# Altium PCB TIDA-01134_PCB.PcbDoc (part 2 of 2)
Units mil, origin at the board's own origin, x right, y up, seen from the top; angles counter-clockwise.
Board outline 4724.41 x 2283.46 mil, 2 copper layers (Top Layer, Bottom Layer), stack 62 mil thick; 90 components, 33 nets, 177 pads, 316 vias.
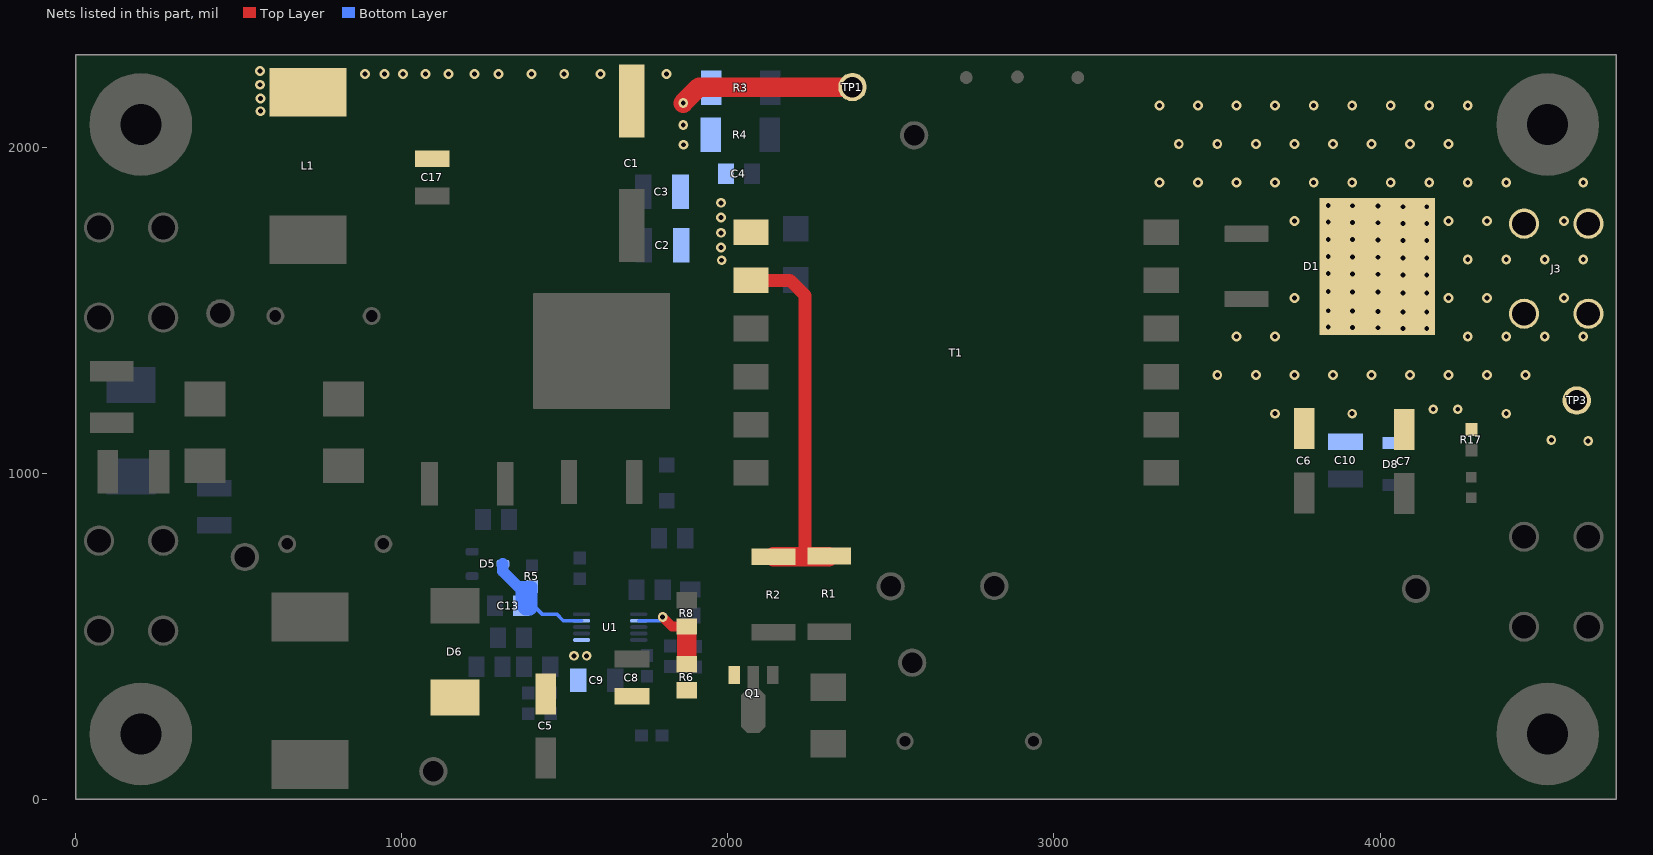
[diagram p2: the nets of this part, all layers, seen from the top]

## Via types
v1: diameter 30, hole 15, Top Layer to Bottom Layer, 316 vias

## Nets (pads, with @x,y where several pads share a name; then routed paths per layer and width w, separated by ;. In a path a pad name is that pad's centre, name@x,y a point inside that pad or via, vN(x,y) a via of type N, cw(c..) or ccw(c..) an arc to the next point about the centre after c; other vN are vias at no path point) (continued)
UVLO: R6.1 R8.2 U1.7 | length 233.5
  Top Layer w30: v1(1800,559) 1829,530 R8.2@1874,530
  Top Layer w60: R6.1@1874,427 R8.2@1874,508
  Bottom Layer w11: U1.7@1726.6,547.68 1792.68,547.68 v1@1793,548
VCC: C13.1 D5.3 R5.1 U1.4 | length 458.7
  Bottom Layer w11: 1410,588 1430,568 1475,568 1495.32,547.68 U1.4@1551.4,547.68
  Bottom Layer w35: D5.3@1310.24,722 1310.24,698.76 1356.5,652.5 ; 1356.5,652.5 R5.1@1399,652.5 1399,586 1394,581 1379,581 C13.1@1366,594 1366,643 1356.5,652.5
VIN: C5.1 C8.1 C9.1 D6.1 Q1.3 R6.2 U1.1
  other v1: 1528,440 1567,440
VIN_FILT: C1.1 C2.1 C3.1 C4.1 C17.1 L1.2 R1.2 R2.2 R3.2 R4.2 T1.1 T1.2 TP1.1 | length 1684.3
  Top Layer w40: T1.2@2071.06,1591.46 2190.54,1591.46 2237,1545 2237,757 ; R1.2@2309,744.14 R1.2@2311,746.14
  Top Layer w60: v1(1863,2135) 1912,2184 TP1.1@2382,2184 ; R2.2@2140,744.14 R1.2@2309,744.14
  other v1: 1981,1653 1979,1692 1979,1737 1979,1784 1979,1829 1864,2007 1863,2068 567,2110 567,2149 565,2191 887,2224 947,2224 1004,2224 1073,2224 1143,2224 1223,2224 1297,2224 1398,2224 1498,2224 1609,2224 1812,2224 565,2233
VOUT: C6.1 C7.1 C10.1 D1.4 D8.1 J3.1 J3.2 J3.3 J3.4 R17.2 TP3.1
  other v1: 4638,1099 4525,1102 3678.08,1182.53 3914.3,1182.53 4386.74,1182.53 4163,1196 4238,1196 3500.91,1300.64 3619.02,1300.64 3737.13,1300.64 3855.24,1300.64 3973.35,1300.64 4091.46,1300.64 4209.57,1300.64 4327.68,1300.64 4445.79,1300.64 3559.97,1418.76 3678.08,1418.76 4268.63,1418.76 4386.74,1418.76 4504.85,1418.76 4622.96,1418.76 4070,1444 4143,1444 3993,1446 3915,1447 3841,1448 4070,1494 4143,1494 3993,1496 3915,1497 3841,1498 3737.13,1536.87 4209.57,1536.87 4327.68,1536.87 4563.9,1536.87 4070,1553 4143,1553 3993,1555 3915,1556 3841,1557 4070,1608 4143,1608 3993,1610 3915,1611 3841,1612 4268.63,1654.98 4386.74,1654.98 4504.85,1654.98 4622.96,1654.98 4070,1660 4143,1660 3993,1662 3915,1663 3841,1664 4070,1713 4143,1713 3993,1715 3915,1716 3841,1717 4070,1766 4143,1766 3993,1768 3915,1769 3841,1770 3737.13,1773.09 4209.57,1773.09 4327.68,1773.09 4563.9,1773.09 4070,1817 4143,1817 3993,1819 3915,1820 3841,1821 3323.75,1891.2 3441.86,1891.2 3559.97,1891.2 3678.08,1891.2 3796.19,1891.2 3914.3,1891.2 4032.41,1891.2 4150.52,1891.2 4268.63,1891.2 4386.74,1891.2 4622.96,1891.2 3382.8,2009.31 3500.91,2009.31 3619.02,2009.31 3737.13,2009.31 3855.24,2009.31 3973.35,2009.31 4091.46,2009.31 4209.57,2009.31 3323.75,2127.42 3441.86,2127.42 3559.97,2127.42 3678.08,2127.42 3796.19,2127.42 3914.3,2127.42 4032.41,2127.42 4150.52,2127.42 4268.63,2127.42
pads on no net: D1.1 D5.2 FID1.1 FID2.1 FID3.1 H1.1 H2.1 H3.1 H4.1 H5.0 H6.0 H7.0 H8.0 LBL1.0 T1.9 T1.10

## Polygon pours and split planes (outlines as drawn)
CS_RS on Top Layer "TOP_LAYER_CS_RS_P082" (solid, remove dead copper, pour order 82): 1288,1036 1298,1046 1382,1046 1398,1030 1398,877 1398,835 1388,825 1353.54,825 1292,886.54 1292,982 1290,984
VIN_FILT on Top Layer "TOP_LAYER_VIN_FILT_P034" (solid, remove dead copper, pour order 34): 542,2112 571.5,2082.5 867,2082.5 912,2052 912,1983 966,1936 1146,1936 1192,1976 1817,1976 1949,1844 1949,1586 1987,1548 2210,1548 2256,1594 2256,1993 2322,2059 2323,2060 2323,2283.46 572.46,2283.46 542,2253
NetC16_1 on Top Layer "TOP_LAYER_NETC16_1_P028" (solid, remove dead copper, pour order 28): 638,1804 560,1804 527,1771 527,1476 574,1429 609,1429 669,1369 682,1369 737,1314 737,1184 760,1161 921,1161 945,1185 945,1307 879,1373 799,1373 764,1408 764,1514 764,1590 788,1614 800,1626 835,1626 865,1656 865,1778 839,1804 637,1804
NetC19_2 on Top Layer "TOP_LAYER_NETC19_2_P026" (solid, remove dead copper, pour order 26): 793,1075.79 750.79,1075.79 721,1046 721,1026 623,928 623,669 588,634 512,634 481,603 481,502 510,473 905,473 929,497 929,623 916,636 799,636 763,672 763,800 763,905 805,947 901,947 920,966 920,1055 900.16,1074.84
NetC18_1 on Top Layer "TOP_LAYER_NETC18_1_P024" (solid, remove dead copper, pour order 24): 367,1349 299,1281 299,1192 329,1162 539,1162 563,1186 563,1315 529,1349 367,1349
48V- on Top Layer "TOP_LAYER_48V-_P020" (solid, remove dead copper, pour order 20): 228,1080.77 285.23,1080.77 451.23,1080.77 487,1045 487,788 456,757 380,757 324,701 324,-2 4,-2 2,0 0,2 0,825 26,851 206,851 224,869 224,916 224,1075.77 229,1080.77
NetC22_2 on Top Layer "TOP_LAYER_NETC22_2_P002" (solid, remove dead copper, pour order 2): 47,1194 0,1147 0,981 46,935 132,935 132,1104 145.69,1114 173,1114 184,1125 184,1180 170,1194
48V+ on Top Layer "TOP_LAYER_48V+_P000" (solid, remove dead copper, pour order 0): -2,2284 0,2282 0,1318 0,1312 30,1282 31,1283 182,1283 255,1356 255,1396 348,1489 348,2283.46
NetQ2_1 on Top Layer "TOP_LAYER_NETQ2_1_P036" (solid, remove dead copper, pour order 36): 1484,1040 1499,1055 1503,1055 1578,1055 1601,1032 1601,906 1586,891 1492,891 1484,899
SW_NODE on Top Layer "TOP_LAYER_SW_NODE_P048" (solid, remove dead copper, pour order 48): 1232.87,1699 1161,1622.94 1161,1138 1194,1105 1756.31,1105 1870,1191.76 1870,1205 1913,1255 2137,1255 2171,1289 2171,1447 2135,1483 1983,1483 1946,1483 1853,1576 1637,1576 1514,1699
VIN on Top Layer "TOP_LAYER_VIN_P050" (solid, remove dead copper, pour order 50): 1491,470 1491.45,469.55 1585,469.55 1596,458.55 1596,349 1604,341 1808,341 1821,341 1839,359 1952,359 1990,397 2001,408 2036,408 2036,350 2034,348 1987,348 1917,278 1537,278 1510,251 1065,251 1027,289 1027,331 1066,370 1362,370 1381,389 1381,419 1431,469
NetD3_1 on Top Layer "TOP_LAYER_NETD3_1_P054" (solid, remove dead copper, pour order 54): 2244,540 2244,549 2257,562 2380,562 2414,528 2414,328 2388,302 2221,302 2170,353 2121,353 2119,355 2119,407 2129,417 2232,417 2244,429
GND on Top Layer "TOP_LAYER_GND_P064" (solid, remove dead copper, pour order 64): -3,2288 3,2282 2256,2282 2256,1 2255,0 2252,3 0,3
NetD1_3 on Top Layer "TOP_LAYER_NETD1_3_P068" (solid, remove dead copper, pour order 68): 3263.39,1546 3427.58,1546 3488.63,1484.95 3638.64,1484.95 3663,1509.31 3663,1751 3617,1797 3232.39,1797 3201.39,1766 3201.39,1578
VOUT on Top Layer "TOP_LAYER_VOUT_P070" (solid, remove dead copper, pour order 70): 3462.83,1295 3497.83,1260 3527,1260 3634,1164 3634,1109.65 3679.47,1071 4718.41,1071 4718.41,2280.59 4717,2282 3282,2282 3207,2207 3207,1876.45 3256.43,1845 3650.7,1845 3714,1789 3714,1490.35 3662,1438.35 3487,1438.35 3462.83,1414.17
ISO_GND on Top Layer "TOP_LAYER_ISO_GND_P074" (solid, remove dead copper, pour order 74): 3211,3 4713,2 4716,-1 4716,1005 3211,1005 3211,5 3209,3
GND on Top Layer "TOP_LAYER_GND_LV" (solid, remove dead copper, pour order 58): 1056,664 957,565 957,222 917,182 576,182 576,-2 2541,-2 2572,29 2572,274 2420,329 2187,329 2129,387 2129,533 2129,653 1045,653
ISO_GND on Top Layer "TOP_LAYER_ISO_GND_P080" (solid, remove dead copper, pour order 80): 3262,1187 3213,1138 3208,1138 3209,1137 3209,921 3268,862 3430,862 3506,862 3561,917 3561,1133 3505,1189 3264,1189
GND on Bottom Layer "BOTTOM_LAYER_GND_LV" (solid, remove dead copper, pour order 78): 1056,664 957,565 957,222 917,182 576,182 576,-2 2541,-2 2572,29 2572,274 2420,329 2187,329 2129,387 2129,533 2129,653 1045,653
EARTH on Bottom Layer "BOTTOM_LAYER_EARTH_P032" (solid, remove dead copper, pour order 32): 931,1571 898,1538 898,1390 898,1377 847,1326 773,1326 689,1242 689,1027 761,955 855,955 900,910 900,734 936,698 965,698 990,723 990,1537 956,1571 930,1571
48V- on Bottom Layer "BOTTOM_LAYER_48V-_P006" (solid, remove dead copper, pour order 6): -2,832 31,865 36,865 479,865 524,820 524,0 1,0
48V+ on Bottom Layer "BOTTOM_LAYER_48V+_P004" (solid, remove dead copper, pour order 4): 0,1265 0,1252 37,1215 244,1215 284,1255 284,1366 287,1369 332,1414 332,2283.46 3,2283.46
VIN_FILT on Bottom Layer "BOTTOM_LAYER_VIN_FILT_P038" (solid, remove dead copper, pour order 38): 1925,2283 1938,2283 1986,2235 1986,1983 2021,1948 2021,1649 2005,1633 1845,1633 1825,1653 1825,2244.46 1864,2283.46
SW_NODE on Bottom Layer "BOTTOM_LAYER_SW_NODE_P040" (solid, remove dead copper, pour order 40): 1306,1140 1838,1140 1918,1220 2230,1220 2359,1349 2360,1348 2360,1319 2360,1575 2302,1633 2140,1633 2082,1575 1640,1575 1593,1622 1593,1765 1544,1814 1298,1814 1249,1765 1249,1200
VIN_FILT on Bottom Layer "BOTTOM_LAYER_VIN_FILT_P042" (solid, remove dead copper, pour order 42): 1941,2084 1844,2084 1807,2121 887,2121 851,2085 544,2085 513,2116 513,2251.46 545,2283.46 1833.54,2283.46 1941,2176
VIN on Bottom Layer "BOTTOM_LAYER_VIN_P044" (solid, remove dead copper, pour order 44): 1530,494 1521,494 1509,482 1509,320 1520,309 1574,309 1586,321 1586,481 1573,494
GND on Bottom Layer "BOTTOM_LAYER_GND_P046" (solid, remove dead copper, pour order 46): 1585,664 1598,677 1721,677 1729,669 1729,589 1738,589 1752,575 1752,567 1748,563 1699,563 1693,557 1693,424 1705,412 1921,412 1949,384 1949,277 1907,235 1449,235 1437,247 1437,275 1445,283 1567,283 1586,302
SS on Bottom Layer "BOTTOM_LAYER_SS_P052" (solid, remove dead copper, pour order 52): 1706,490 1705,490 1701,486 1701,452 1732,421 1770.7,421 1770.7,480.3 1761,490
NetC4_2 on Bottom Layer "BOTTOM_LAYER_NETC4_2_P056" (solid, remove dead copper, pour order 56): 2131,2283.46 2094,2246.46 2094,1986 2057,1949 2049,1949 2049,1884 2061,1872 2081,1872 2165,1788 2165,1713 2168,1710 2273,1710 2298,1735 2298,2266.46 2281,2283.46
NetC19_2 on Bottom Layer "BOTTOM_LAYER_NETC19_2_P060" (solid, remove dead copper, pour order 60): 698,817 749,817 765,801 765,743 754,732 706,732 690,748 689,749 689,805
NetC16_1 on Bottom Layer "BOTTOM_LAYER_NETC16_1_P062" (solid, remove dead copper, pour order 62): 696,1515 747,1515 763,1499 763,1441 752,1430 704,1430 688,1446 687,1447 687,1503
GND on Bottom Layer "BOTTOM_LAYER_GND_P066" (solid, remove dead copper, pour order 66): -3,2289 3,2283 2256,2283 2256,2 2255,1 2252,4 0,4
VOUT on Bottom Layer "BOTTOM_LAYER_VOUT_P072" (solid, remove dead copper, pour order 72): 3677,1070 4716,1070 4716,2280 3283,2280 3209,2206 3209,1429 3209,1258 3436,1258 3531.9,1258 3634,1164 3634,1109
ISO_GND on Bottom Layer "BOTTOM_LAYER_ISO_GND_P076" (solid, remove dead copper, pour order 76): 3211,3 4713,2 4716,-1 4716,1007 3211,1007 3211,5 3209,3
EARTH on Bottom Solder "NONET_L-01_P-001" (solid): 895,1357 990,1357 990,933 899,933 861,971 786,971 718,1039 718,1254 775,1311 849,1311

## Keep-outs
Keep-Out Layer:
  the board outline again, w10
  text ".Layer_Name" at 577,-858.49 h60

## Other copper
Top Layer:
  pour cut-out: 913,1670 914,1669 914,1535 976,1473 996,1473 996,752 942,698 836,698 792,742 792,903 800,911 901,911 953,963 953,1155 951,1157 955,1157 972,1174 972,1329 930,1371 930,1392 871,1451 869,1449 819,1449 802,1466 802,1582 824,1582 911,1669
  pour cut-out: 3185,1536 3435,1536 3462,1509 3462,1271 3432,1241 3393,1241 3204,1241 3183,1262 3183,1274
  pour cut-out: 3464,1817 3468,1821 3653,1821 3662,1812 3662,1788 3656,1782 3638,1782 3627,1771 3479,1771
  text ".Layer_Name" at 577,-858.49 h60
Bottom Layer:
  text ".Layer_Name" at 577,-858.49 h60

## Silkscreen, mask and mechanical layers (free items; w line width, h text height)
Top Overlay:
  region: 3835,522 3535,522 3535,422 3835,422
  text "Vin_FILT" at 2076,2109 h60
  text "SW_Node" at 2660,2019 h60
  text "48V+" at 114,1832 h60
  text "Vout" at 4318,1627 h60 r90
  text "48V+" at 373,1366 h60
  text "Vout" at 4442,1161 h60 r90
  text "48V-" at 391,808 h60 r270
  text "FB-" at 2539,750 h60
  text "V+" at 2854,750 h60
  text "GND" at 2610,516 h60
  text "ISO_GND" at 3918,509 h60
  text "ISO_GND" at 4325,449 h60 r90
  text "48V-" at 103.2,391 h60
  text "'.PRJ_Number'.PCB_Rev" at 3403,149 h108.27
  text "Vin=10V-80V DC, 100V Transient  Vout=12V" at 3076,13 h60
  text ".Layer_Name" at 577,-858.49 h60
Bottom Overlay:
  text ".Layer_Name" at 577,-858.49 h60
Top Paste:
  text ".Layer_Name" at 577,-858.49 h60
Bottom Paste:
  text ".Layer_Name" at 577,-858.49 h60
Top Solder:
  text ".Layer_Name" at 577,-858.49 h60
  text ".Layer_Name" at 577,-858.49 h60
Bottom Solder:
  text ".Layer_Name" at 577,-858.49 h60
Drill Guide:
  text ".Layer_Name" at 577,-858.49 h60
M1 Board Outline:
  the board outline again, w10
  text ".Layer_Name" at 577,-858.49 h60
M2 Board Dimensions:
  rectangle: 125,-400 500,-275
  rectangle: 0,-275 125,-150
  lines w7: 0,-275 1000,-275 ; 125,-400 125,-150 ; 250,-400 250,-150 ; 500,-400 500,-150 ; 750,-400 750,-150 ; 0,-400 0,-150 1000,-150 1000,-400 0,-400
  text ".Layer_Name" at 577,-858.49 h60
M3 3D STEP Top:
  text ".Layer_Name" at 577,-858.49 h60
M4 3D STEP Bottom:
  text ".Layer_Name" at 577,-858.49 h60
M5 Assembly Top:
  lines w10: -292,-930.17 6308,-930.17 ; -292,-726.83 6310,-726.83 ; -292,-523.5 -292,-1133.5 3713,-1133.5 6310,-1133.5 6310,-523.5 -291.5,-523.5 -291.5,-1133.5 1284,-1133.5 ; 2173,-1133.5 2173,-523.5 ; 3440,-726.83 3440,-523.5 ; 4280,-726.83 4280,-523.5 ; 4902,-1140 4902,-937.17
  text "COMPONENTS MARKED 'DNP' SHOULD NOT BE POPULATED." at 1153.5,-318.5 h60
  text "ASSEMBLY VARIANT:" at 1153,-434 h60
  text ".VariantName" at 2189,-434 h60
  text "PCB VIEWED FROM TOP SIDE" at -228.5,-655.67 h60
  text "BOARD #:" at 2248,-655.67 h60
  text ".PRJ_Number" at 2793.5,-655.67 h60
  text "REV:" at 3638,-655.67 h60
  text ".PCB_Rev" at 3929.5,-655.67 h60
  text "SVN REV:" at 4476,-655.67 h60
  text ".VersionControl_RevNumber" at 4982,-655.67 h60
  text "TID #:" at 2248,-859 h60
  text ".TID" at 2793.5,-859 h60
  text "PLOT NAME =" at -228.5,-1064.34 h60
  text ".plot_File_Name" at 577,-1064.34 h60
  text "GENERATED    :" at 2250,-1064.34 h60
  text ".Print_Date" at 3119.5,-1064.34 h60
  text ".Print_Time" at 3848.5,-1064.34 h60
  text "TEXAS INSTRUMENTS" at 5113,-1064.34 h60
M6 Assembly Bottom:
  lines w10: -292.5,-727.33 6309.5,-727.33 ; -290.5,-930.67 6309.5,-930.67 ; 1115.5,-1140.5 1115.5,-937.67 ; 1737.5,-727.33 1737.5,-524 ; 2577.5,-727.33 2577.5,-524 ; 3844.5,-1134 3844.5,-524 ; 4733.5,-1134 6309,-1134 6309,-524 -292.5,-524 -292.5,-1134 2304.5,-1134 6309.5,-1134 6309.5,-524
  text "COMPONENTS MARKED 'DNP' SHOULD NOT BE POPULATED." at 6102,-318 h60
  text ".VariantName" at 5058,-434 h60
  text "ASSEMBLY VARIANT:" at 6097,-434 h60
  text ".VersionControl_RevNumber" at 1035.5,-656.17 h60
  text "SVN REV:" at 1541.5,-656.17 h60
  text ".PCB_Rev" at 2088,-656.17 h60
  text "REV:" at 2379.5,-656.17 h60
  text ".PRJ_Number" at 3224,-656.17 h60
  text "BOARD #:" at 3769.5,-656.17 h60
  text "PCB VIEWED FROM BOTTOM SIDE" at 6246,-656.17 h60
  text ".TID" at 3224,-859.5 h60
  text "TID #:" at 3769.5,-859.5 h60
  text "TEXAS INSTRUMENTS" at 904.5,-1064.84 h60
  text ".Print_Time" at 2169,-1064.84 h60
  text ".Print_Date" at 2898,-1064.84 h60
  text "GENERATED    :" at 3767.5,-1064.84 h60
  text ".plot_File_Name" at 5440.5,-1064.84 h60
  text "PLOT NAME =" at 6246,-1064.84 h60
M9 Title Sheet:
  drawing of 57 lines, arcs and shapes, not listed
  text "1" at 739.84,8036.5 h70
  text "2" at 3235.5,8036.5 h70
  text "3" at 5724.84,8036.5 h70
  text "4" at 8231.51,8036.5 h70
  text "5" at 10730.5,8036.5 h70
  text "6" at 13235.5,8036.5 h70
  text "A" at -416.5,6893.5 h70
  text "A" at 14383.5,6893.5 h70
  text "B" at -416.5,4513.5 h70
  text "B" at 14383.5,4513.5 h70
  text "C" at -416.5,2138.5 h70
  text "C" at 14383.5,2138.5 h70
  text "PROJECT TITLE:" at 11343.5,277.5 h45
  text ".PRJ_Title" at 11393.5,144.17 h70
  text "DESIGNED FOR:" at 11343.5,-23.5 h45
  text ".PRJ_Customer" at 11393.5,-163.5 h70
  text "D" at -416.5,-231.5 h70
  text "D" at 14383.5,-231.5 h70
  text "FILE NAME:" at 11343.5,-323.5 h45
  text ".PCB_File_Name_No_Path" at 11393.5,-443.5 h70
  text "Texas Instruments (TI) and/or its licensors do not warrant the accuracy or completeness of this specification" at 6374,-605.34 h45
  text "ENGINEER:" at 11343.5,-613.5 h45
  text "LAYOUT BY:" at 12848.5,-613.5 h45
  text "or any information contained therein. TI and/or its licensors do not warrant that this design will meet" at 6329.01,-718 h45
  text ".PRJ_Engineer" at 11393.5,-768.49 h70
  text ".PCB_Layout" at 12899,-768.49 h70
  text "the specifications, will be suitable for your application or fit for any particular purpose, or will operate in" at 6329.01,-830.67 h45
  text ".Layer_Name" at 577,-858.49 h60
  text "ALTIUM DESIGNER VERSION:" at 12848.5,-923.5 h45
  text "an implementation. TI and/or its licensors do not warrant that the design is production worthy. You should" at 6329.01,-943.33 h45
  text "completely validate and test your design implementation to confirm the system functionality for your application." at 6374,-1056 h45
  text ".print_Scale" at 11393.5,-1056.83 h70
  text ".Application_BuildNumber" at 12899,-1056.83 h70
  text "1" at 739.84,-1263.5 h70
  text "2" at 3235.5,-1263.5 h70
  text "3" at 5724.84,-1263.5 h70
  text "4" at 8231.51,-1263.5 h70
  text "5" at 10730.5,-1263.5 h70
  text "6" at 13235.5,-1263.5 h70
M10 Fab Notes:
  drawing of 173 lines, arcs and shapes, not listed
  text "DESIGN INFORMATION" at 12378.02,6201 h60
  text "MIN. TRACK WIDTH:" at 11733.46,6021 h60
  text "8" at 12829.7,6021 h60
  text "MIL" at 12984.46,6021 h60
  text "MIN. CLEARANCE:" at 11733.46,5889 h60
  text "0.2" at 12769.7,5889 h60
  text "mm" at 12984.46,5889 h60
  text "MIN. VIA PAD SIZE:" at 11733.46,5757 h60
  text "24" at 12799.71,5757 h60
  text "MIL" at 12984.46,5757 h60
  text "0.05mm (2MIL)" at 12428.46,5615.29 h60
  text "MINIMUM ANNULAR RING" at 11404.23,5611 h60
  text "EXTERNAL" at 13136.46,5611 h60
  text "PER" at 11604.23,5493 h60
  text "IPC-D-275 CLASS 2 LEVEL C" at 11824.23,5493 h60
  text "MIL, HOLES" at 13312.46,5380.71 h60
  text "+/-" at 12920,5380 h60
  text "+/-" at 13774,5380 h60
  text "REGISTRATION TOLERANCES:" at 11404.23,5375 h60
  text "METAL" at 12604,5375 h60
  text "5" at 13180.2,5375 h60
  text "3" at 14013.2,5375 h60
  text "MIL" at 14129.46,5375 h60
  text "+/-" at 13774,5262 h60
  text "HOLE SIZE TOLERANCE (UNLESS OTHERWISE SPECIFIED):" at 11404.23,5257 h60
  text "3" at 14013.2,5257 h60
  text "MIL" at 14129.46,5257 h60
  text "MATERIAL:" at 11329.46,5047.54 h60
  text "FR-4 High Tg" at 12315.9,4907.21 h60
  text "FR-408" at 11750.46,4898.64 h60
  text "OTHER" at 13238.46,4898.64 h60
  text "X" at 12161,4895 h60
  text "62 MIL (1.6mm) +/-10%" at 12070.56,4735.92 h60
  text "THICKNESS:" at 11404.23,4731.64 h60
  text "X" at 11942.4,4731.64 h60
  text "OTHER" at 13355.46,4731.64 h60
  text "TOLERANCE:" at 11404.23,4573.64 h60
  text "X" at 12243.53,4573.64 h60
  text "ANSI IPC-6012 TYPE 3 CLASS 2" at 12430.48,4573.64 h60
  text "OTHER +/-" at 12430.46,4417.64 h60
  text "BOW & TWIST:" at 11404.23,4260.64 h60
  text "X" at 12243.53,4260.64 h60
  text "ANSI IPC-6012 TYPE 3 CLASS 2" at 12430.48,4260.64 h60
  text "OTHER +/-" at 12430.46,4102.13 h60
  text "DRILLING:" at 11329.46,3963.64 h60
  text "REFERENCE:" at 11404.23,3846.64 h60
  text "X" at 12052.46,3846.64 h60
  text "AS SHOWN" at 12239.46,3846.64 h60
  text "X" at 12953.46,3846.64 h60
  text "NC_DRILL FILES" at 13090.46,3846.64 h60
  text "PTH COPPER THICKNESS:" at 11404.23,3688.64 h60
  text "X" at 12534.46,3688.64 h60
  text "20-30 um" at 12671.46,3688.64 h60
  text "OTHER" at 13388.46,3688.64 h60
  text "BOARD FINISH:" at 11329.46,3529.64 h60
  text "SILKSCREEN:" at 11484.68,3411.64 h60
  text "X" at 12433.46,3411.64 h60
  text "TOP" at 12559.46,3411.64 h60
  text "X" at 12943.46,3411.64 h60
  text "BOTTOM" at 13070.46,3411.64 h60
  text "SILKSCREEN COLOR:" at 11484.68,3244.64 h60
  text "X" at 12432.42,3244.64 h60
  text "WHITE" at 12559.46,3244.64 h60
  text "OTHER" at 13070.46,3244.64 h60
  text "X" at 12563.42,3085.44 h60
  text "GREEN" at 12690.46,3085.44 h60
  text "OTHER" at 13308.46,3085.44 h60
  text "SOLDER RESIST COLOR:" at 11484.68,3074.64 h60
  text "X" at 12563.42,2915.44 h60
  text "MATTE" at 12690.46,2915.44 h60
  text "SEMI-GLOSS" at 13308,2914.8 h60
  text "IMMERSION GOLD (ENIG)" at 12390.46,2726.92 h60
  text "ENEPIG" at 13728,2723.64 h60
  text "SURFACE FINISH:" at 11329.46,2722.64 h60
  text "X" at 12203.51,2722.64 h60
  text "IMM. TIN/SILVER OR EQUIV" at 11659,2565.64 h60
  text "OTHER" at 13090.46,2565.64 h60
  text "ARRAY/PANEL:" at 11329.46,2386.64 h60
  text "CUT AND TRIM PER M1 BOARD OUTLINE" at 12390.46,2382.35 h60
  text "N.C. ROUTE" at 12390.46,2230.64 h60
  text "X" at 13069.46,2230.64 h60
  text "V. SCORE" at 13256.46,2230.64 h60
  text "CERTIFICATION:" at 11329.46,2093.64 h60
  text "MATERIALS AND WORKMANSHIP FOR ALL PCBS" at 12054.46,2093.64 h60
  text "TO MEET OR EXCEED THE REQUIREMENTS OF:" at 12054.46,1995.64 h60
  text "X" at 11680.96,1859.13 h60
  text "ANSI IPC-A-600F CLASS ->" at 11819.96,1859.13 h60
  text "X" at 13459.02,1859.13 h60
  text "2" at 13577.96,1859.14 h60
  text "1" at 13262.96,1857.64 h60
  text "3" at 13931.96,1857.64 h60
  text "X" at 12495.02,1699.64 h60
  text "RoHS" at 12631.96,1699.64 h60
  text "OTHER" at 13276.36,1699.64 h60
  text "PER ORDER" at 13673.42,1699.64 h60
  text "ALL BOARDS MUST MEET OR EXCEED UL94-V0 REQUIREMENTS." at 11357,1534 h60
  text "PCB MUST BEAR THE UL94V-0 UL REGISTERED MATERIAL ID NUMBER" at 11357,1414 h60
  text "ADDITIONAL REQUIREMENTS:" at 11329.46,1240.64 h60
  text "MICROSECTION:" at 11404.23,1125.64 h60
  text "YES" at 12309.96,1125.64 h60
  text "REQUIRED" at 13171.46,969.49 h60
  text "BARE BOARD ELEC. TEST:" at 11404.23,966.64 h60
  text "NONE" at 12709.96,966.64 h60
  text "X" at 13044.46,966.64 h60
  text "PER ORDER" at 13763.46,966.64 h60
  text ".Layer_Name" at 577,-858.49 h60
M11 Gerber Information:
  lines w10: -292,-930.17 6308,-930.17 ; -292,-726.83 6310,-726.83 ; -292,-523.5 -292,-1133.5 3713,-1133.5 6310,-1133.5 6310,-523.5 -291.5,-523.5 -291.5,-1133.5 1284,-1133.5 ; 2173,-1133.5 2173,-523.5 ; 3440,-726.83 3440,-523.5 ; 4280,-726.83 4280,-523.5 ; 4902,-1140 4902,-937.17
  text "ALL ARTWORK VIEWED FROM TOP SIDE" at -228.5,-655.67 h60
  text "BOARD #:" at 2248,-655.67 h60
  text ".PRJ_Number" at 2793.5,-655.67 h60
  text "REV:" at 3638,-655.67 h60
  text ".PCB_Rev" at 3929.5,-655.67 h60
  text "SVN REV:" at 4476,-655.67 h60
  text ".VersionControl_RevNumber" at 4982,-655.67 h60
  text "LAYER NAME =" at -228.5,-858.49 h60
  text "TID #:" at 2248,-859 h60
  text ".TID" at 2793.5,-859 h60
  text "PLOT NAME =" at -228.5,-1064.34 h60
  text ".plot_File_Name" at 577,-1064.34 h60
  text "GENERATED    :" at 2250,-1064.34 h60
  text ".Print_Date" at 3119.5,-1064.34 h60
  text ".Print_Time" at 3848.5,-1064.34 h60
  text "TEXAS INSTRUMENTS" at 5113,-1064.34 h60
M12 Stackup:
  drawing of 191 lines, arcs and shapes, not listed
  text "Layer" at 9707,7670 h60
  text "Name" at 10116.91,7670 h60
  text "Material" at 11046.66,7670 h60
  text "Thickness" at 11906.42,7670 h60
  text "Constant" at 12556.26,7670 h60
  text "Board Layer Stack" at 13126.12,7670 h60
  text "1" at 9707,7550 h60
  text "Top Overlay" at 10116.91,7550 h60
  text "2" at 9707,7430 h60
  text "Top Solder" at 10116.91,7430 h60
  text "Solder Resist" at 11046.66,7430 h60
  text "0.40mil" at 11906.42,7430 h60
  text "3.5" at 12556.26,7430 h60
  text "3" at 9707,7310 h60
  text "Top Layer" at 10116.91,7310 h60
  text "Copper" at 11046.66,7310 h60
  text "1.40mil" at 11906.42,7310 h60
  text "4" at 9707,7190 h60
  text "Dielectric1" at 10116.91,7190 h60
  text "FR-4" at 11046.66,7190 h60
  text "59.20mil" at 11906.42,7190 h60
  text "4.8" at 12556.26,7190 h60
  text "5" at 9707,7070 h60
  text "Bottom Layer" at 10116.91,7070 h60
  text "Copper" at 11046.66,7070 h60
  text "1.40mil" at 11906.42,7070 h60
  text "6" at 9707,6950 h60
  text "Bottom Solder" at 10116.91,6950 h60
  text "Solder Resist" at 11046.66,6950 h60
  text "0.40mil" at 11906.42,6950 h60
  text "3.5" at 12556.26,6950 h60
  text "7" at 9707,6830 h60
  text "Bottom Overlay" at 10116.91,6830 h60
  text ".Layer_Name" at 577,-858.49 h60
M13 Component Bodies Top:
  text ".Layer_Name" at 577,-858.49 h60
M14 Component Bodies Bottom:
  text ".Layer_Name" at 577,-858.49 h60
M15 Courtyards Top:
  text ".Layer_Name" at 577,-858.49 h60
M16 Courtyards Bottom:
  text ".Layer_Name" at 577,-858.49 h60
Drill Drawing:
  circle w10: c5760.73,4826.58 r27.63
  lines w10: 5733.1,4923.29 5788.36,4923.29 5788.36,4978.55 5733.1,4978.55 5733.1,4923.29 ; 5733.1,5102.89 5788.36,5102.89 5760.73,5047.62 5733.1,5102.89 ; 5733.1,5185.78 5746.91,5185.78 5760.73,5171.96 5774.54,5185.78 5788.36,5185.78 5774.54,5199.59 5788.36,5213.41 5774.54,5213.41 5760.73,5227.22 5746.91,5213.41 5733.1,5213.41 5746.91,5199.59 5733.1,5185.78 ; 5733.1,5296.3 5760.73,5310.11 5788.36,5296.3 5774.54,5323.93 5788.36,5351.56 5760.73,5337.74 5733.1,5351.56 5746.91,5323.93 5733.1,5296.3 ; 5733.1,5434.45 5746.91,5434.45 5746.91,5420.63 5774.54,5420.63 5774.54,5434.45 5788.36,5434.45 5788.36,5462.08 5774.54,5462.08 5774.54,5475.89 5746.91,5475.89 5746.91,5462.08 5733.1,5462.08 5733.1,5434.45
  lines w12: 5683,4761.65 8913.06,4761.65 ; 5683,5507.66 8913.06,5507.66 ; 6020.75,4637.32 6020.75,5632 ; 6352.56,4637.32 6352.56,5632 ; 6988.66,4637.32 6988.66,5632 ; 7247.66,4637.32 7247.66,5632 ; 7622.64,4637.32 7622.64,5632 ; 8346.86,4637.32 8346.86,5632 ; 5683,4637.32 8913.06,4637.32 8913.06,5632 5683,5632 5683,4637.32
  text "Symbol" at 5757.6,5544.97 h72
  text "Quantity" at 6058.05,5544.97 h72
  text "Finished Hole Size" at 6389.86,5544.97 h72
  text "Plated" at 7025.96,5544.97 h72
  text "Hole Type" at 7284.96,5544.97 h72
  text "Drill Layer Pair" at 7659.94,5544.97 h72
  text "Hole Tolerance" at 8384.16,5544.97 h72
  text "316" at 6058.05,5420.63 h60
  text "15.00mil (0.381mm)" at 6389.86,5420.63 h60
  text "PTH" at 7025.96,5420.63 h60
  text "Round" at 7284.96,5420.63 h60
  text "Top Layer - Bottom Layer" at 7659.94,5420.63 h60
  text "2" at 6058.05,5296.3 h60
  text "33.46mil (0.850mm)" at 6389.86,5296.3 h60
  text "PTH" at 7025.96,5296.3 h60
  text "Round" at 7284.96,5296.3 h60
  text "Top Layer - Bottom Layer" at 7659.94,5296.3 h60
  text "4" at 6058.05,5171.96 h60
  text "35.43mil (0.900mm)" at 6389.86,5171.96 h60
  text "PTH" at 7025.96,5171.96 h60
  text "Round" at 7284.96,5171.96 h60
  text "Top Layer - Bottom Layer" at 7659.94,5171.96 h60
  text "10" at 6058.05,5047.62 h60
  text "63.00mil (1.600mm)" at 6389.86,5047.62 h60
  text "PTH" at 7025.96,5047.62 h60
  text "Round" at 7284.96,5047.62 h60
  text "Top Layer - Bottom Layer" at 7659.94,5047.62 h60
  text "16" at 6058.05,4923.29 h60
  text "72.83mil (1.850mm)" at 6389.86,4923.29 h60
  text "PTH" at 7025.96,4923.29 h60
  text "Round" at 7284.96,4923.29 h60
  text "Top Layer - Bottom Layer" at 7659.94,4923.29 h60
  text "4" at 6058.05,4798.95 h60
  text "125.98mil (3.200mm)" at 6389.86,4798.95 h60
  text "PTH" at 7025.96,4798.95 h60
  text "Round" at 7284.96,4798.95 h60
  text "Top Layer - Bottom Layer" at 7659.94,4798.95 h60
  text "352 Total" at 6058.05,4674.62 h60
  text ".Layer_Name" at 577,-858.49 h60
M17 Embedded Cavity:
  text ".Layer_Name" at 577,-858.49 h60
M18 Embedded Assembly:
  text ".Layer_Name" at 577,-858.49 h60
M19 Embedded Keepout:
  text ".Layer_Name" at 577,-858.49 h60

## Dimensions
0,0 to 4724.41,0 on M2 Board Dimensions
0,-400 to 1000,-400 on M2 Board Dimensions
0,0 to 0,2283.46 on M2 Board Dimensions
